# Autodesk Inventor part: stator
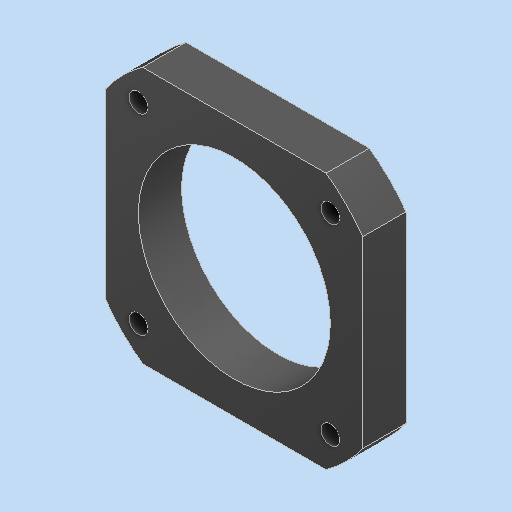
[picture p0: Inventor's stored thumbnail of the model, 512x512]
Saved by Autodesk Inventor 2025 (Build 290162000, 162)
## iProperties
Created: 2025-05
Part Number: stator
Material: Generico
Description: stator
Document SubType Name: Modeling
Designer: R5800u
Density: 1 g/cm^3
Appearance: Default
Author: R5800u
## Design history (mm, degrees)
feature "Base1"
node "Solido1"
